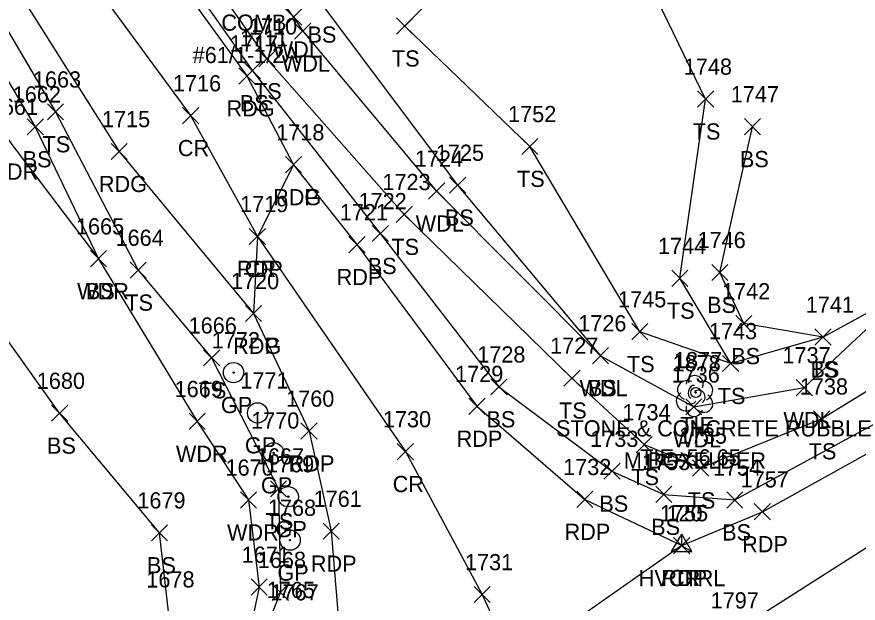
# Model space of a CAD drawing. Extents: x 1647133 to 1649138, y 411736 to 414924.
# Drawn here: x 1648964.6 to 1649068.5, y 412279.3 to 412351.7 of the extents above; entities that cross this region are included whole.
import ezdxf

# ---------------------------------------------------------------- set-up
doc = ezdxf.new("R2010")
doc.units = 0
for name, color, linetype in [('C_A', 7, 'Continuous'), ('C_C', 7, 'Continuous'), ('C_I', 7, 'Continuous'), ('CBP', 7, 'Continuous'), ('CPSM', 7, 'Continuous'), ('L_A', 7, 'Continuous'), ('L_C', 7, 'Continuous'), ('L_I', 7, 'Continuous'), ('L_TIC', 7, 'Continuous'), ('LAWA', 7, 'Continuous'), ('LELB', 7, 'Continuous'), ('LTD', 7, 'Continuous'), ('P_A', 7, 'Continuous'), ('P_I', 7, 'Continuous'), ('P_TIC', 7, 'Continuous'), ('PET', 7, 'Continuous'), ('PEU', 7, 'Continuous'), ('PRC', 7, 'Continuous'), ('R_A', 7, 'Continuous'), ('R_I', 7, 'Continuous'), ('RGP', 7, 'Continuous'), ('S_I', 7, 'Continuous'), ('U_A', 7, 'Continuous'), ('U_C', 7, 'Continuous')]:
    doc.layers.add(name, color=color, linetype=linetype)

msp = doc.modelspace()

# ---------------------------------------------------------------- linework, layer by layer
at = {"layer": 'CBP'}
for radius in [0.625, 0.0833]:
    msp.add_circle((1649048.41, 412305.31), radius, dxfattribs=at)
at = {"layer": 'CPSM'}
for p, q in [((1649045.43, 412285.69), (1649046.68, 412287.85)), ((1649047.93, 412285.69), (1649046.68, 412287.85)), ((1649046.68, 412286.41), (1649046.68, 412287.85)), ((1649045.43, 412285.69), (1649046.68, 412286.41)), ((1649046.68, 412286.41), (1649046.68, 412286.41)), ((1649046.68, 412286.41), (1649047.93, 412285.69)), ((1649045.43, 412285.69), (1649047.93, 412285.69))]:
    msp.add_line(p, q, dxfattribs=at)
at = {"layer": 'L_TIC'}
for points in [[(1648997.78, 412350.65), (1648999.78, 412352.65)], [(1648999.78, 412350.65), (1648997.78, 412352.65)], [(1648998.91, 412348.91), (1649000.91, 412350.91)], [(1649000.91, 412348.91), (1648998.91, 412350.91)], [(1649011.5, 412349.54), (1649013.5, 412351.54)], [(1649013.5, 412349.54), (1649011.5, 412351.54)], [(1648994.49, 412345.49), (1648996.49, 412347.49)], [(1648996.49, 412345.49), (1648994.49, 412347.49)], [(1648992.7, 412344.02), (1648994.7, 412346.02)], [(1648994.7, 412344.02), (1648992.7, 412346.02)], [(1649048.63, 412340.53), (1649050.63, 412342.53)], [(1649050.63, 412340.53), (1649048.63, 412342.53)], [(1648968.4, 412338.95), (1648970.4, 412340.95)], [(1648970.4, 412338.95), (1648968.4, 412340.95)], [(1649054.42, 412337.12), (1649056.42, 412339.12)], [(1649056.42, 412337.12), (1649054.42, 412339.12)], [(1648965.91, 412337.1), (1648967.91, 412339.1)], [(1648967.91, 412337.1), (1648965.91, 412339.1)], [(1649026.94, 412334.68), (1649028.94, 412336.68)], [(1649028.94, 412334.68), (1649026.94, 412336.68)], [(1649026.94, 412334.68), (1649028.94, 412336.68)], [(1649028.94, 412334.68), (1649026.94, 412336.68)], [(1649018.02, 412329.9), (1649020.02, 412331.9)], [(1649020.02, 412329.9), (1649018.02, 412331.9)], [(1649015.43, 412329.17), (1649017.43, 412331.17)], [(1649017.43, 412329.17), (1649015.43, 412331.17)], [(1649011.44, 412326.29), (1649013.44, 412328.29)], [(1649013.44, 412326.29), (1649011.44, 412328.29)], [(1649008.48, 412323.93), (1649010.48, 412325.93)], [(1649010.48, 412323.93), (1649008.48, 412325.93)], [(1648973.71, 412320.82), (1648975.71, 412322.82)], [(1648975.71, 412320.82), (1648973.71, 412322.82)], [(1648973.71, 412320.82), (1648975.71, 412322.82)], [(1648975.71, 412320.82), (1648973.71, 412322.82)], [(1648978.6, 412319.41), (1648980.6, 412321.41)], [(1648980.6, 412319.41), (1648978.6, 412321.41)], [(1649050.38, 412319.13), (1649052.38, 412321.13)], [(1649052.38, 412319.13), (1649050.38, 412321.13)], [(1649045.44, 412318.41), (1649047.44, 412320.41)], [(1649047.44, 412318.41), (1649045.44, 412320.41)], [(1649053.35, 412312.81), (1649055.35, 412314.81)], [(1649055.35, 412312.81), (1649053.35, 412314.81)], [(1649040.51, 412311.82), (1649042.51, 412313.82)], [(1649042.51, 412311.82), (1649040.51, 412313.82)], [(1649063.12, 412311.16), (1649065.12, 412313.16)], [(1649065.12, 412311.16), (1649063.12, 412313.16)], [(1649063.12, 412311.16), (1649065.12, 412313.16)], [(1649065.12, 412311.16), (1649063.12, 412313.16)], [(1648987.67, 412308.59), (1648989.67, 412310.59)], [(1648989.67, 412308.59), (1648987.67, 412310.59)], [(1649035.65, 412308.86), (1649037.65, 412310.86)], [(1649037.65, 412308.86), (1649035.65, 412310.86)], [(1649035.65, 412308.86), (1649037.65, 412310.86)], [(1649037.65, 412308.86), (1649035.65, 412310.86)], [(1649051.72, 412307.89), (1649053.72, 412309.89)], [(1649053.72, 412307.89), (1649051.72, 412309.89)], [(1649051.72, 412307.89), (1649053.72, 412309.89)], [(1649053.72, 412307.89), (1649051.72, 412309.89)], [(1649032.13, 412306.09), (1649034.13, 412308.09)], [(1649034.13, 412306.09), (1649032.13, 412308.09)], [(1649023.13, 412305.01), (1649025.13, 412307.01)], [(1649025.13, 412305.01), (1649023.13, 412307.01)], [(1649060.81, 412304.92), (1649062.81, 412306.92)], [(1649062.81, 412304.92), (1649060.81, 412306.92)], [(1649047.18, 412302.54), (1649049.18, 412304.54)], [(1649049.18, 412302.54), (1649047.18, 412304.54)], [(1648968.91, 412301.76), (1648970.91, 412303.76)], [(1648970.91, 412301.76), (1648968.91, 412303.76)], [(1649062.94, 412301.06), (1649064.94, 412303.06)], [(1649064.94, 412301.06), (1649062.94, 412303.06)], [(1648985.89, 412300.75), (1648987.89, 412302.75)], [(1648987.89, 412300.75), (1648985.89, 412302.75)], [(1649041.05, 412297.88), (1649043.05, 412299.88)], [(1649043.05, 412297.88), (1649041.05, 412299.88)], [(1649037.07, 412294.6), (1649039.07, 412296.6)], [(1649039.07, 412294.6), (1649037.07, 412296.6)], [(1649048.01, 412295), (1649050.01, 412297)], [(1649050.01, 412295), (1649048.01, 412297)], [(1648995.92, 412292.43), (1648997.92, 412294.43)], [(1648997.92, 412292.43), (1648995.92, 412294.43)], [(1649043.47, 412291.74), (1649045.47, 412293.74)], [(1649045.47, 412291.74), (1649043.47, 412293.74)], [(1648992.21, 412291.05), (1648994.21, 412293.05)], [(1648994.21, 412291.05), (1648992.21, 412293.05)], [(1649052.23, 412291.05), (1649054.23, 412293.05)], [(1649054.23, 412291.05), (1649052.23, 412293.05)], [(1648981.24, 412287), (1648983.24, 412289)], [(1648983.24, 412287), (1648981.24, 412289)], [(1648993.54, 412280.3), (1648995.54, 412282.3)], [(1648995.54, 412280.3), (1648993.54, 412282.3)], [(1648996.15, 412279.66), (1648998.15, 412281.66)], [(1648998.15, 412279.66), (1648996.15, 412281.66)]]:
    msp.add_lwpolyline(points, dxfattribs=at)
at = {"layer": 'LAWA'}
for points in [[(1648980.94, 412375.36), (1648998.78, 412351.65), (1648999.91, 412349.91), (1649016.43, 412330.17), (1649036.65, 412309.86), (1649048.18, 412303.54), (1649061.81, 412305.92), (1649074.48, 412317.81)], [(1648951.05, 412353.82), (1648963.52, 412336.58), (1648974.71, 412321.82), (1648986.89, 412301.75), (1648993.21, 412292.05), (1648994.54, 412281.3), (1648991.32, 412266.13), (1648987.65, 412250.05), (1648975.93, 412241.95)]]:
    msp.add_lwpolyline(points, dxfattribs=at)
at = {"layer": 'LELB'}
for points in [[(1648977.8, 412371.73), (1648995.49, 412346.49), (1649012.44, 412327.29), (1649033.13, 412307.09), (1649042.05, 412298.88), (1649049.01, 412296), (1649063.94, 412302.06), (1649078.74, 412311.15)], [(1648975.88, 412370.36), (1648993.7, 412345.02), (1649009.48, 412324.93), (1649024.13, 412306.01), (1649038.07, 412295.6), (1649044.47, 412292.74), (1649053.23, 412292.05), (1649080.64, 412306.97)], [(1649052.72, 412308.89), (1649046.44, 412319.41), (1649049.63, 412341.53), (1649041.01, 412359.3), (1649021.59, 412359.85), (1649012.5, 412350.54), (1649027.94, 412335.68)], [(1648958.6, 412358.35), (1648969.4, 412339.95), (1648979.6, 412320.41), (1648988.67, 412309.59), (1648996.92, 412293.43), (1648997.15, 412280.66), (1648991.32, 412266.13)], [(1648955.83, 412356.84), (1648966.91, 412338.1), (1648974.71, 412321.82)], [(1649002.06, 412353.49), (1649019.02, 412330.9), (1649036.65, 412309.86)], [(1649074.48, 412317.81), (1649064.12, 412312.16), (1649054.35, 412313.81), (1649051.38, 412320.13), (1649055.42, 412338.12)], [(1649064.12, 412312.16), (1649052.72, 412308.89), (1649041.51, 412312.82), (1649027.94, 412335.68)], [(1648975.7, 412250.53), (1648977.59, 412262.81), (1648981.91, 412271.44), (1648983.35, 412278.25), (1648982.24, 412288), (1648969.91, 412302.76), (1648958.57, 412318.59), (1648952.7, 412330.5)]]:
    msp.add_lwpolyline(points, dxfattribs=at)
at = {"layer": 'LTD'}
msp.add_line((1649048.24, 412304.93), (1649048.24, 412304.93), dxfattribs=at)
msp.add_line((1649048.24, 412304.93), (1649048.24, 412304.93), dxfattribs=at)
msp.add_arc((1649048.29, 412306.36), 1.05, 335.5272, 180.9563, dxfattribs=at)
for centre, major_axis, ratio, start_param, end_param in [((1649047.45, 412305.59), (1.21, -0.51), 0.895232, 1.570796, 4.712389), ((1649048.03, 412305.39), (-0.208, -0.792), 0.645439, 3.141593, 6.283185), ((1649049.28, 412305.51), (-1.14, -0.48), 0.949671, 1.570796, 4.712389), ((1649047.16, 412304.22), (0.58, -1.04), 0.959034, 3.141593, 6.283185), ((1649048.74, 412304.76), (-0.5, 0.667), 0.989748, 3.141593, 6.283185), ((1649049.24, 412304.09), (-1.09, 0.79), 0.841452, 1.570796, 4.712389), ((1649047.78, 412304.18), (-0.625, -0.083), 0.423636, 0, 3.141593), ((1649048.24, 412303.43), (0.26, 1.06), 0.942809, 1.570796, 4.712389)]:
    msp.add_ellipse(centre, major_axis=major_axis, ratio=ratio, start_param=start_param, end_param=end_param, dxfattribs=at)
at = {"layer": 'P_TIC'}
for points in [[(1648992.02, 412343.38), (1648994.02, 412345.38)], [(1648994.02, 412343.38), (1648992.02, 412345.38)], [(1648985.07, 412338.48), (1648987.07, 412340.48)], [(1648987.07, 412338.48), (1648985.07, 412340.48)], [(1648976.26, 412334.05), (1648978.26, 412336.05)], [(1648978.26, 412334.05), (1648976.26, 412336.05)], [(1648997.77, 412332.42), (1648999.77, 412334.42)], [(1648999.77, 412332.42), (1648997.77, 412334.42)], [(1648997.77, 412332.42), (1648999.77, 412334.42)], [(1648999.77, 412332.42), (1648997.77, 412334.42)], [(1648997.77, 412332.42), (1648999.77, 412334.42)], [(1648999.77, 412332.42), (1648997.77, 412334.42)], [(1648993.31, 412323.57), (1648995.31, 412325.57)], [(1648995.31, 412323.57), (1648993.31, 412325.57)], [(1648993.31, 412323.57), (1648995.31, 412325.57)], [(1648995.31, 412323.57), (1648993.31, 412325.57)], [(1649005.6, 412322.57), (1649007.6, 412324.57)], [(1649007.6, 412322.57), (1649005.6, 412324.57)], [(1648992.83, 412314.07), (1648994.83, 412316.07)], [(1648994.83, 412314.07), (1648992.83, 412316.07)], [(1648992.83, 412314.07), (1648994.83, 412316.07)], [(1648994.83, 412314.07), (1648992.83, 412316.07)], [(1649020.41, 412302.61), (1649022.41, 412304.61)], [(1649022.41, 412302.61), (1649020.41, 412304.61)], [(1648999.69, 412299.56), (1649001.69, 412301.56)], [(1649001.69, 412299.56), (1648999.69, 412301.56)], [(1649011.58, 412297.02), (1649013.58, 412299.02)], [(1649013.58, 412297.02), (1649011.58, 412299.02)], [(1649033.73, 412291.12), (1649035.73, 412293.12)], [(1649035.73, 412291.12), (1649033.73, 412293.12)], [(1649055.64, 412289.6), (1649057.64, 412291.6)], [(1649057.64, 412289.6), (1649055.64, 412291.6)], [(1649002.42, 412287.2), (1649004.42, 412289.2)], [(1649004.42, 412287.2), (1649002.42, 412289.2)], [(1649045.68, 412285.42), (1649047.68, 412287.42)], [(1649047.68, 412285.42), (1649045.68, 412287.42)], [(1649045.68, 412285.42), (1649047.68, 412287.42)], [(1649047.68, 412285.42), (1649045.68, 412287.42)], [(1649021.05, 412279.38), (1649023.05, 412281.38)], [(1649023.05, 412279.38), (1649021.05, 412281.38)]]:
    msp.add_lwpolyline(points, dxfattribs=at)
at = {"layer": 'PET'}
for points in [[(1648998.77, 412333.42), (1648994.31, 412324.57), (1648993.83, 412315.07), (1649000.69, 412300.56), (1649003.42, 412288.2), (1649004.9, 412270.19), (1649001.61, 412254.48), (1648993.91, 412243.99), (1648984.63, 412233.46), (1648979.62, 412228.92), (1648985.33, 412222.55), (1648990.49, 412216.93), (1649002.33, 412227.19), (1649016.43, 412237.44), (1649036.67, 412252.92), (1649058.78, 412267.78), (1649074.29, 412277.9), (1649090.06, 412287.47)], [(1648998.77, 412333.42), (1649006.6, 412323.57), (1649021.41, 412303.61), (1649034.73, 412292.12), (1649046.68, 412286.42), (1649056.64, 412290.6), (1649081.58, 412304.46)]]:
    msp.add_lwpolyline(points, dxfattribs=at)
at = {"layer": 'PEU'}
for points in [[(1648974.78, 412369.55), (1648993.02, 412344.38), (1648998.77, 412333.42)], [(1648961.22, 412360.43), (1648977.26, 412335.05), (1648993.83, 412315.07)]]:
    msp.add_lwpolyline(points, dxfattribs=at)
at = {"layer": 'PRC'}
for points in [[(1648967.33, 412365.01), (1648986.07, 412339.48), (1648994.31, 412324.57), (1649012.58, 412298.02), (1649022.05, 412280.38), (1649025.93, 412271.86), (1649001.61, 412254.48)], [(1648985.33, 412222.55), (1648998.03, 412233.46), (1649011.26, 412245.34), (1649030.66, 412261.2), (1649052.94, 412275.66), (1649084.88, 412295.99)], [(1649046.68, 412286.42), (1649025.93, 412271.86)]]:
    msp.add_lwpolyline(points, dxfattribs=at)
at = {"layer": 'RGP'}
for p, q in [((1648991.37, 412307.77), (1648991.37, 412307.77)), ((1648994.34, 412302.8), (1648994.34, 412302.8)), ((1648996.32, 412297.86), (1648996.32, 412297.86)), ((1648998.12, 412292.46), (1648998.12, 412292.46)), ((1648998.35, 412287.09), (1648998.35, 412287.09))]:
    msp.add_line(p, q, dxfattribs=at)
for centre, radius in [((1648991.37, 412307.77), 1.25), ((1648991.37, 412307.77), 0.0833), ((1648994.34, 412302.8), 1.25), ((1648994.34, 412302.8), 0.0833), ((1648996.32, 412297.86), 1.25), ((1648996.32, 412297.86), 0.0833), ((1648998.12, 412292.46), 1.25), ((1648998.12, 412292.46), 0.0833), ((1648998.35, 412287.09), 1.25), ((1648998.35, 412287.09), 0.0833)]:
    msp.add_circle(centre, radius, dxfattribs=at)

# ---------------------------------------------------------------- texts
at = {"layer": 'C_A'}
for s, p in [('TIE', (1649046.49, 412300.31)), ('HVCTRL', (1649041.37, 412281.41))]:
    msp.add_text(s, height=2, dxfattribs=at).set_placement(p)
at = {"layer": 'C_C'}
msp.add_text('TIE=56.65', height=2, dxfattribs=at).set_placement((1649041.55, 412296.31))
at = {"layer": 'C_I'}
for s, p in [('1877', (1649045.72, 412308.31)), ('120', (1649044.8, 412289.41))]:
    msp.add_text(s, height=2, dxfattribs=at).set_placement(p)
at = {"layer": 'L_A'}
for s, p in [('BS', (1649000.5, 412348.49)), ('BS', (1649000.5, 412348.49)), ('WDL', (1648996.2, 412346.65)), ('TS', (1649010.91, 412345.54)), ('WDL', (1648997.33, 412344.91)), ('TS', (1648993.9, 412341.49)), ('BS', (1648992.14, 412340.02)), ('TS', (1649048.04, 412336.53)), ('TS', (1648967.8, 412334.95)), ('BS', (1648965.35, 412333.1)), ('BS', (1649053.86, 412333.12)), ('WDR', (1648960.88, 412331.58)), ('TS', (1649026.35, 412330.68)), ('TS', (1649026.35, 412330.68)), ('BS', (1649017.46, 412325.9)), ('WDL', (1649013.85, 412325.17)), ('TS', (1649010.85, 412322.29)), ('BS', (1649007.93, 412319.93)), ('WDR', (1648972.07, 412316.82)), ('BS', (1648973.15, 412316.82)), ('TS', (1648978.01, 412315.41)), ('TS', (1649044.85, 412314.41)), ('BS', (1649049.82, 412315.13)), ('BS', (1649052.79, 412308.81)), ('TS', (1649039.92, 412307.82)), ('TS', (1649062.53, 412307.16)), ('BS', (1649062.56, 412307.16)), ('TS', (1648987.08, 412304.59)), ('WDL', (1649034.07, 412304.86)), ('BS', (1649035.1, 412304.86)), ('TS', (1649051.13, 412303.89)), ('TS', (1649051.13, 412303.89)), ('TS', (1649031.54, 412302.09)), ('BS', (1649022.58, 412301.01)), ('WDL', (1649059.22, 412300.92)), ('H', (1649047.67, 412299.93)), ('BS', (1648968.35, 412297.76)), ('WDL', (1649045.6, 412298.54)), ('WDR', (1648984.26, 412296.75)), ('TS', (1649062.35, 412297.06)), ('TS', (1649040.46, 412293.88)), ('BS', (1649036.51, 412290.6)), ('TS', (1649047.42, 412291)), ('TS', (1648995.33, 412288.43)), ('BS', (1649042.91, 412287.74)), ('WDR', (1648990.57, 412287.05)), ('BS', (1649051.67, 412287.05)), ('BS', (1648980.69, 412283))]:
    msp.add_text(s, height=2, dxfattribs=at).set_placement(p)
at = {"layer": 'L_C'}
for s, p in [('STONE & CONCRETE RUBBLE', (1649031.17, 412299.89)), ('STONE & CONCRETE RUBBLE', (1649031.17, 412299.89)), ('M.BOXELDER', (1649039.54, 412295.93))]:
    msp.add_text(s, height=2, dxfattribs=at).set_placement(p)
at = {"layer": 'L_I'}
for s, p in [('1710', (1648993.27, 412349.49)), ('1711', (1648992.14, 412348.02)), ('1748', (1649046.93, 412344.53)), ('1663', (1648966.61, 412342.95)), ('1662', (1648964.12, 412341.1)), ('1747', (1649052.73, 412341.12)), ('1661', (1648961.3, 412339.58)), ('1752', (1649025.25, 412338.68)), ('1752', (1649025.25, 412338.68)), ('1724', (1649013.74, 412333.17)), ('1725', (1649016.33, 412333.9)), ('1723', (1649009.74, 412330.29)), ('1722', (1649006.79, 412327.93)), ('1665', (1648971.92, 412324.82)), ('1665', (1648971.92, 412324.82)), ('1664', (1648976.81, 412323.41)), ('1746', (1649048.63, 412323.13)), ('1744', (1649043.75, 412322.41)), ('1742', (1649051.65, 412316.81)), ('1745', (1649038.82, 412315.82)), ('1741', (1649061.99, 412315.16)), ('1741', (1649061.99, 412315.16)), ('1666', (1648985.83, 412312.59)), ('1726', (1649033.91, 412312.86)), ('1726', (1649033.91, 412312.86)), ('1743', (1649050.03, 412311.89)), ('1743', (1649050.03, 412311.89)), ('1727', (1649030.44, 412310.09)), ('1728', (1649021.44, 412309.01)), ('1737', (1649059.11, 412308.92)), ('1878', (1649045.55, 412307.93)), ('1736', (1649045.43, 412306.54)), ('1680', (1648967.09, 412305.76)), ('1738', (1649061.25, 412305.06)), ('1669', (1648984.1, 412304.75)), ('1734', (1649039.36, 412301.88)), ('1735', (1649046.32, 412299)), ('1733', (1649035.38, 412298.6)), ('1667', (1648994.13, 412296.43)), ('1753', (1649041.78, 412295.74)), ('1670', (1648990.38, 412295.05)), ('1754', (1649050.53, 412295.05)), ('1679', (1648979.5, 412291)), ('1671', (1648992.37, 412284.3)), ('1668', (1648994.36, 412283.66)), ('1678', (1648980.61, 412281.25))]:
    msp.add_text(s, height=2, dxfattribs=at).set_placement(p)
at = {"layer": 'P_A'}
for s, p in [('RDG', (1648990.51, 412339.38)), ('CR', (1648984.5, 412334.48)), ('RDG', (1648974.75, 412330.05)), ('RDG', (1648996.25, 412328.42)), ('RDP', (1648996.25, 412328.42)), ('RDP', (1648996.25, 412328.42)), ('RDP', (1648991.8, 412319.57)), ('CR', (1648992.75, 412319.57)), ('RDP', (1649004.09, 412318.57)), ('RDG', (1648991.32, 412310.07)), ('RDP', (1648991.32, 412310.07)), ('RDP', (1649018.9, 412298.61)), ('RDP', (1648998.18, 412295.56)), ('CR', (1649011.01, 412293.02)), ('RDP', (1649032.22, 412287.12)), ('RDP', (1649054.13, 412285.6)), ('RDP', (1649000.91, 412283.2)), ('RDP', (1649044.17, 412281.42)), ('CR', (1649045.11, 412281.42))]:
    msp.add_text(s, height=2, dxfattribs=at).set_placement(p)
at = {"layer": 'P_I'}
for s, p in [('1717', (1648990.9, 412347.38)), ('1716', (1648983.89, 412342.48)), ('1715', (1648975.13, 412338.05)), ('1718', (1648996.64, 412336.42)), ('1718', (1648996.64, 412336.42)), ('1718', (1648996.64, 412336.42)), ('1719', (1648992.18, 412327.57)), ('1719', (1648992.18, 412327.57)), ('1721', (1649004.48, 412326.57)), ('1720', (1648991.05, 412318.07)), ('1720', (1648991.05, 412318.07)), ('1729', (1649018.71, 412306.61)), ('1760', (1648997.86, 412303.56)), ('1730', (1649009.8, 412301.02)), ('1732', (1649032.04, 412295.12)), ('1757', (1649053.95, 412293.6)), ('1761', (1649001.25, 412291.2)), ('1755', (1649043.99, 412289.42)), ('1755', (1649043.99, 412289.42)), ('1731', (1649019.93, 412283.38)), ('1797', (1649050.25, 412278.66))]:
    msp.add_text(s, height=2, dxfattribs=at).set_placement(p)
at = {"layer": 'R_A'}
for p in [(1648989.81, 412302.77), (1648992.77, 412297.8), (1648994.75, 412292.86), (1648996.55, 412287.46), (1648996.78, 412282.09)]:
    msp.add_text('GP', height=2, dxfattribs=at).set_placement(p)
at = {"layer": 'R_I'}
for s, p in [('1772', (1648988.68, 412310.77)), ('1771', (1648992.21, 412305.8)), ('1770', (1648993.54, 412300.86)), ('1769', (1648995.37, 412295.46)), ('1768', (1648995.61, 412290.09)), ('1767', (1648995.93, 412279.66))]:
    msp.add_text(s, height=2, dxfattribs=at).set_placement(p)
at = {"layer": 'S_I'}
msp.add_text('1765', height=2, dxfattribs=at).set_placement((1648995.47, 412279.95))
at = {"layer": 'U_A'}
msp.add_text('COMB', height=2, dxfattribs=at).set_placement((1648989.87, 412349.96))
at = {"layer": 'U_C'}
msp.add_text('#61/1-1/2A', height=2, dxfattribs=at).set_placement((1648986.33, 412345.96))

doc.saveas('drawing.dxf')
